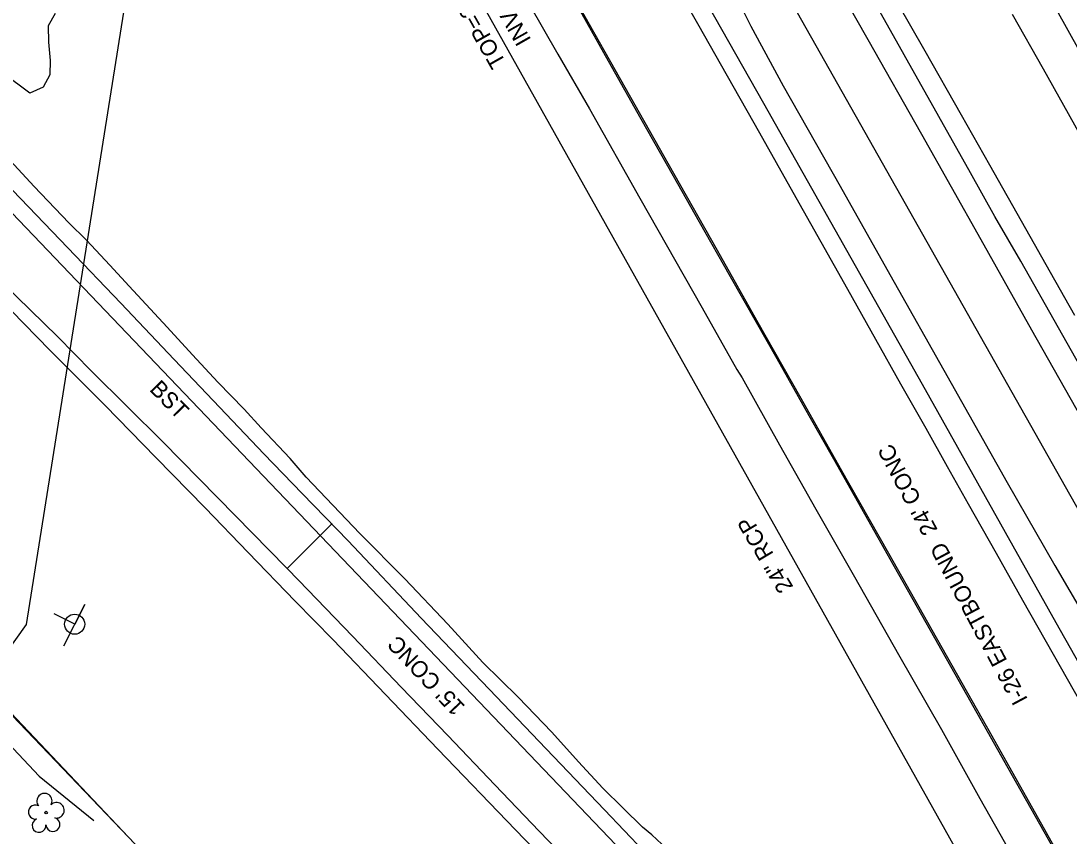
# Model space of a CAD drawing. Extents: x 945964 to 948456, y 631061 to 636061.
# Drawn here: x 947091.5 to 947347.7, y 633431.8 to 633631 of the extents above; entities that cross this region are included whole.
import ezdxf

# ---------------------------------------------------------------- set-up
doc = ezdxf.new("R2010")
doc.units = 0
for name, color, linetype in [('Exist Boundary County Line', 7, 'Continuous'), ('Exist Guardrail', 7, 'Continuous'), ('Exist Horizontal Alignment', 7, 'Continuous'), ('Exist Other Culture Area Outline', 7, 'Continuous'), ('Exist Other Culture Fence Line', 7, 'Continuous'), ('Exist Right of Way Line', 7, 'Continuous'), ('Exist Roads Change in Surface', 7, 'Continuous'), ('Exist Roads EOP', 7, 'Continuous'), ('Exist Roads EOT', 7, 'Continuous'), ('Exist Roads EOT Text', 7, 'Continuous'), ('Exist Structure Minor Drop Inlet Top Elevation', 7, 'Continuous'), ('Exist Structure Minor Pipes RCP 24 Inch', 7, 'Continuous'), ('Exist Structure Minor Pipes RCP 24 Inch Invert', 7, 'Continuous'), ('Exist Structure Minor Pipes RCP 24 Inch Text', 7, 'Continuous'), ('Exist Utilities Power Joint Use Telephone CELL', 7, 'Continuous'), ('Exist Utilities TV UG FO Cable SUE', 7, 'Continuous'), ('Exist Vegetation Hedge Row', 7, 'Continuous'), ('Exist Vegetation Tree CELL', 7, 'Continuous')]:
    doc.layers.add(name, color=color, linetype=linetype)

# ---------------------------------------------------------------- blocks, each defined once
blk = doc.blocks.new('EXIST UTILITIES POWER JOINT USE TELEPHONE')
at = {"layer": 'Exist Utilities Power Joint Use Telephone CELL'}
blk.add_line((0, 0), (0, 0), dxfattribs=at)
blk.add_lwpolyline([(-0.1188, 0), (0.108, -0.0008), (0, -0.0004), (0, 0.1125)], dxfattribs=at)
blk.add_circle((0, 0.0001), 0.049, dxfattribs=at)

msp = doc.modelspace()

# ---------------------------------------------------------------- linework, layer by layer
at = {"layer": 'Exist Boundary County Line'}
for p, q in [((947148.44, 633833.66), (947092.82, 633483.47)), ((947092.82, 633483.47), (946827.48, 633113.91))]:
    msp.add_line(p, q, dxfattribs=at)
at = {"layer": 'Exist Guardrail'}
for points in [[(947379.92, 633481.81), (947369.5, 633500.97), (947353.59, 633529.09), (947338.63, 633555.45), (947326.23, 633577.53), (947311.75, 633603.27), (947298.65, 633626.41), (947286.61, 633647.67), (947275.07, 633668.11), (947263.79, 633688.07), (947251.02, 633710.76), (947236.35, 633736.7), (947221.15, 633763.38), (947204.15, 633793.65), (947187.76, 633822.78), (947171.28, 633852.16), (947157.63, 633876.42), (947140.96, 633906.1), (947126.61, 633931.62), (947125.32, 633933.93)], [(947268.37, 633632.99), (947269.99, 633629.77), (947277.86, 633615.12), (947291.76, 633590.66), (947303.21, 633570.38), (947318.97, 633542.51), (947332.66, 633518.17), (947344.26, 633497.9), (947355.84, 633478.09)]]:
    msp.add_lwpolyline(points, dxfattribs=at)
at = {"layer": 'Exist Horizontal Alignment'}
for p, q in [((948030.66, 632307.31), (947093.53, 633965.31)), ((947304.2, 633359.41), (946986.05, 633692.01))]:
    msp.add_line(p, q, dxfattribs=at)
at = {"layer": 'Exist Other Culture Area Outline'}
for points in [[(947502.74, 633551.84), (947491.43, 633598.35), (947481.81, 633655.47), (947473.42, 633706.38), (947465.97, 633751.69), (947457.82, 633800.26), (947449.82, 633849.21), (947440.92, 633903.16), (947434.15, 633943.61), (947423.94, 634005.84), (947416.66, 634047.81), (947408.17, 634100.43), (947401.63, 634128.51), (947390.02, 634166.53), (947375.97, 634204.38), (947358.86, 634250.48), (947349.29, 634283.79), (947346.49, 634302.94), (947347.33, 634323.73), (947349.56, 634350.73), (947351.79, 634371.96), (947352.04, 634380.41)], [(947498.1, 633549.11), (947485.93, 633597.25), (947475.95, 633654.8), (947467.52, 633705.53), (947460.23, 633750.52), (947452.1, 633799.7), (947443.77, 633849.62), (947435.12, 633902.3), (947428.36, 633943.07), (947418.1, 634004.56), (947410.76, 634048.74), (947402.29, 634099.82), (947395.78, 634127.82), (947384.42, 634164.9), (947370.55, 634202.66), (947354.33, 634246.12), (947343.66, 634281.62), (947340.62, 634293.86), (947329.49, 634297.96), (947319.27, 634301.42)]]:
    msp.add_spline(points, degree=3, dxfattribs=at)
at = {"layer": 'Exist Other Culture Fence Line'}
msp.add_lwpolyline([(947010.9, 633543.44), (947065.9, 633486.27), (947136.6, 633411.71), (947222.93, 633322.56)], dxfattribs=at)
at = {"layer": 'Exist Right of Way Line'}
msp.add_line((947242.4, 633301.31), (947082.24, 633468.73), dxfattribs=at)
at = {"layer": 'Exist Roads Change in Surface'}
msp.add_lwpolyline([(947156.63, 633497.19), (947167.61, 633508.22), (947167.61, 633508.22)], dxfattribs=at)
at = {"layer": 'Exist Roads EOP'}
for points in [[(947381.86, 633418.11), (947344.63, 633483.93), (947311.93, 633542.13), (947273.16, 633610.8), (947247.15, 633656.74)], [(947353.51, 633618.03), (947341.56, 633639.47)], [(947363.62, 633523.42), (947335.96, 633572.27), (947329.6, 633583.21), (947323.66, 633593.93), (947299.72, 633636.57)], [(947215.81, 633635.13), (947222.82, 633622.86), (947230.49, 633609.56), (947242.83, 633587.7), (947258.03, 633560.93), (947266.55, 633545.85), (947267.87, 633543.76), (947276.99, 633527.42), (947285.82, 633511.7), (947295.33, 633495.12), (947306.08, 633476.19), (947316.54, 633457.86), (947325.95, 633440.96), (947335.7, 633423.72), (947346.8, 633404.28), (947355.93, 633387.89)], [(947249.41, 633428.64), (947245.78, 633432.08), (947243.5, 633433.97), (947238.76, 633438.61), (947233.8, 633443.51), (947227.84, 633449.9), (947221.32, 633457.18), (947213.09, 633465.76), (947204.48, 633474.25), (947195.92, 633483.61), (947185.38, 633494.66), (947174.34, 633505.76), (947161.27, 633519.53), (947157.32, 633524.05), (947150.3, 633531.54), (947146.08, 633536.17), (947139.68, 633542.74), (947133.49, 633549.38), (947127.26, 633556.14), (947118, 633566.18), (947113.26, 633571.29), (947107.54, 633577.45), (947103.28, 633581.65), (947094.81, 633590.56), (947087.91, 633597.93)], [(947360.74, 633277.06), (947337.8, 633301.61), (947314.5, 633326.07), (947296.1, 633345.52), (947275.16, 633367.34), (947258.69, 633384.71), (947243.45, 633401.02), (947228.86, 633416.25), (947212.46, 633433.3), (947193.45, 633453.04), (947180.69, 633466.35), (947167.9, 633479.74), (947158.54, 633489.22), (947147.1, 633501.06), (947136.61, 633512.02), (947124.51, 633524.29), (947112.1, 633537.05), (947098.61, 633550.57), (947085.97, 633563.42)]]:
    msp.add_lwpolyline(points, dxfattribs=at)
at = {"layer": 'Exist Roads EOT'}
for points in [[(947314.32, 633482.12), (947303.69, 633500.88), (947291.91, 633521.61), (947282.28, 633538.71), (947271.42, 633557.81), (947261.78, 633574.88), (947251.15, 633593.72), (947239.22, 633614.73), (947228.09, 633634.46), (947217.81, 633652.59), (947207.58, 633670.63), (947198.12, 633687.54), (947187.85, 633705.81), (947177.86, 633723.68), (947167.77, 633741.49), (947155.84, 633762.61), (947145.18, 633781.37), (947134.93, 633799.64), (947123.53, 633819.69), (947112.95, 633838.27), (947104.79, 633852.86), (947098.28, 633864.4)], [(947350.8, 633464.1), (947343.95, 633476.18), (947336.49, 633489.38), (947330, 633500.85), (947323.21, 633512.94), (947318.03, 633522.06), (947312.81, 633531.43), (947306.65, 633542.27), (947300.51, 633553.18), (947293.7, 633565.34), (947287.16, 633576.93), (947280.3, 633589.11), (947272.13, 633603.61), (947264.25, 633617.53), (947257.02, 633630.3), (947249.1, 633644.21)], [(947349.13, 633559.04), (947343.18, 633569.57), (947337.18, 633580.17), (947328.35, 633595.73), (947321.43, 633608.01), (947312.59, 633623.6), (947302.75, 633640.89)], [(947227.91, 633634.02), (947235.81, 633619.97), (947243.09, 633607.11), (947251, 633593.12), (947257.32, 633581.91), (947264.9, 633568.53), (947271.23, 633557.4), (947276.29, 633548.51), (947284.18, 633534.56), (947290.2, 633523.97), (947297.76, 633510.58), (947305.01, 633497.69), (947313.8, 633482.1)], [(947350.34, 633603.54), (947341.5, 633619.21), (947333.92, 633632.61)], [(947354.83, 633311.35), (947344.68, 633322.11), (947329.98, 633337.62), (947319, 633349.23), (947306.82, 633362.07), (947294.8, 633374.62), (947284.31, 633385.64), (947271.54, 633399.05), (947259.77, 633411.35), (947248.62, 633423.08), (947234.18, 633438.17), (947219.92, 633453.15), (947205.96, 633467.73), (947189.41, 633485.07), (947171.5, 633503.92), (947160.32, 633515.5), (947150.93, 633525.18), (947141.67, 633534.94), (947129.01, 633548.27), (947115.94, 633562), (947103.01, 633575.57), (947087.62, 633591.65)], [(947353.93, 633290.62), (947343.56, 633301.72), (947332.29, 633313.74), (947316.82, 633330.05), (947305.26, 633342.19), (947294.07, 633353.86), (947284.82, 633363.47), (947269.93, 633379.05), (947255.89, 633393.76), (947243.15, 633406.93), (947229.92, 633420.82), (947218.25, 633433.02), (947207.41, 633444.32), (947195.89, 633456.34), (947184.5, 633468.2), (947172.64, 633480.6), (947159.38, 633494.35), (947156.58, 633497.15), (947156.35, 633497.4), (947144.02, 633510.08), (947126.22, 633528.16), (947108.82, 633545.44), (947100.51, 633553.87), (947087.17, 633566.81)], [(947313.8, 633482.1), (947322.66, 633466.42), (947332.76, 633448.48), (947341.57, 633432.91), (947351.06, 633416.14)], [(947543.04, 633070.41), (947547.79, 633063.19), (947560.65, 633042.78), (947572.95, 633022.21), (947579.51, 633010.75), (947590.49, 632991.17), (947591.21, 632991.74), (947580.14, 633011.61), (947565.48, 633037.44), (947550.51, 633064.36), (947536.03, 633090.2), (947521.11, 633116.29), (947505.76, 633142.74), (947488.14, 633174.64), (947472.15, 633202.76), (947447.33, 633246.77), (947427.49, 633281.8), (947404.97, 633321.76), (947375.12, 633374.56), (947348.55, 633421.44), (947328.94, 633456.22), (947314.32, 633482.12)]]:
    msp.add_lwpolyline(points, dxfattribs=at)
at = {"layer": 'Exist Structure Minor Pipes RCP 24 Inch'}
msp.add_line((947191.62, 633657.8), (947394.62, 633295.61), dxfattribs=at)
at = {"layer": 'Exist Utilities TV UG FO Cable SUE'}
msp.add_lwpolyline([(947004.77, 633521.4), (947011.84, 633519.21), (947034.06, 633502.94), (947065.64, 633478.59), (947096.03, 633446.46), (947109.32, 633435.59)], dxfattribs=at)
at = {"layer": 'Exist Vegetation Hedge Row'}
msp.add_lwpolyline([(947099.92, 633632.85), (947098.19, 633629.85), (947098.28, 633625.84), (947098.65, 633621.33), (947098.64, 633617.82), (947097, 633614.83), (947093.72, 633613.33), (947087.3, 633618.15), (947083.42, 633618.78), (947079.93, 633618.87), (947072.6, 633627.77), (947057.7, 633643.28)], dxfattribs=at)
at = {"layer": 'Exist Vegetation Tree CELL'}
msp.add_line((947097.67, 633437.51), (947097.67, 633437.51), dxfattribs=at)
msp.add_circle((947097.67, 633437.51), 0.326, dxfattribs=at)
for centre, radius, start, end in [((947097.29, 633440.38), 1.86, 330.1651, 219.7134), ((947095.07, 633437.67), 1.73, 62.6636, 279.3457), ((947100.22, 633438.1), 1.9, 257.1011, 134.1999), ((947095.97, 633434.39), 1.69, 111.5671, 6.231), ((947099.34, 633434.61), 1.7, 181.2822, 74.56)]:
    msp.add_arc(centre, radius, start, end, dxfattribs=at)

# ---------------------------------------------------------------- block references
at = {"layer": 'Exist Utilities Power Joint Use Telephone CELL', "xscale": 50.00000000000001, "yscale": 50, "rotation": 63.32631113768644}
msp.add_blockref('EXIST UTILITIES POWER JOINT USE TELEPHONE', (947104.67, 633483.57), dxfattribs=at)

# ---------------------------------------------------------------- texts
at = {"layer": 'Exist Roads EOT Text'}
for s, rotation, p in [('BST', 314.2557, (947122.77, 633540.8)), ("I-26 EASTBOUND  24' CONC", 118.0147, (947337.77, 633465.18)), ("15' CONC", 133.3491, (947200.31, 633463.52))]:
    msp.add_text(s, height=4, rotation=rotation, dxfattribs=at).set_placement(p)
at = {"layer": 'Exist Structure Minor Drop Inlet Top Elevation'}
msp.add_text("TOP=2174.85'", height=4, rotation=119.5351, dxfattribs=at).set_placement((947210.21, 633620.84))
at = {"layer": 'Exist Structure Minor Pipes RCP 24 Inch Invert'}
msp.add_text("INV=2170.77'", height=4, rotation=119.5705, dxfattribs=at).set_placement((947216.38, 633626.41))
at = {"layer": 'Exist Structure Minor Pipes RCP 24 Inch Text'}
msp.add_text('24" RCP', height=4, rotation=120.8208, dxfattribs=at).set_placement((947280.44, 633492.68))

doc.saveas('drawing.dxf')
